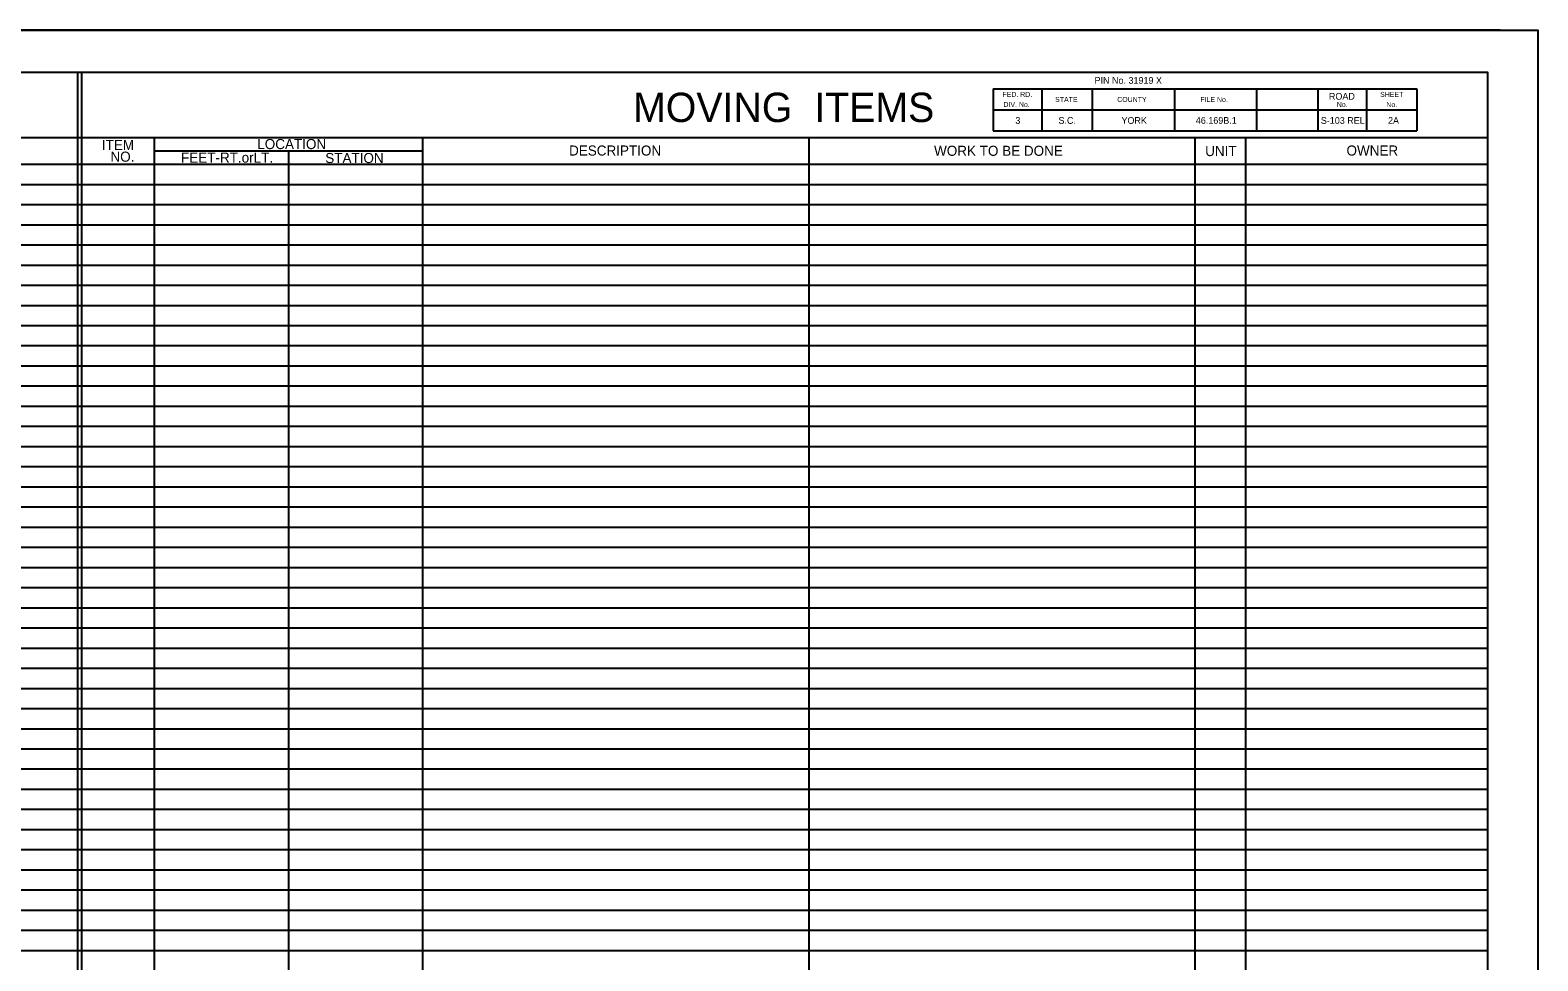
# Model space of a CAD drawing. Extents: x -796 to 2793, y -4650 to 4425.
# Drawn here: x 1884 to 2782, y -1829 to -1275 of the extents above; entities that cross this region are included whole.
import ezdxf

# ---------------------------------------------------------------- set-up
doc = ezdxf.new("R2010")
doc.units = 0
for name, color, linetype in [('RD_HC_CL', 7, 'Continuous'), ('RD_HC_Data', 7, 'Continuous'), ('RD_HC_Data_Tic', 7, 'Continuous')]:
    doc.layers.add(name, color=color, linetype=linetype)

msp = doc.modelspace()

# ---------------------------------------------------------------- linework, layer by layer
at = {"layer": 'RD_HC_CL'}
msp.add_lwpolyline([(986.5, -1275), (2782.45, -1275), (2782.45, -2375), (986.5, -2375)], close=True, dxfattribs=at)
at = {"layer": 'RD_HC_Data'}
for p, q in [((2760, -1275), (1000, -1275)), ((1000, -1275), (2760, -1275)), ((1912.65, -1300), (1912.65, -2350)), ((1915.15, -1300), (1915.15, -2350)), ((2457.95, -1310), (2457.95, -1335)), ((2457.95, -1310), (2710.45, -1310)), ((2486.95, -1310), (2486.95, -1322.5)), ((2516.95, -1310), (2516.95, -1322.5)), ((2565.95, -1310), (2565.95, -1322.5)), ((2614.95, -1310), (2614.95, -1322.5)), ((2651.45, -1310), (2651.45, -1322.5)), ((2680.45, -1310), (2680.45, -1322.5)), ((2710.45, -1310), (2710.45, -1335)), ((2457.95, -1322.5), (2710.45, -1322.5)), ((2486.95, -1322.5), (2486.95, -1335)), ((2516.95, -1322.5), (2516.95, -1335)), ((2565.95, -1322.5), (2565.95, -1335)), ((2614.95, -1322.5), (2614.95, -1335)), ((2651.45, -1322.5), (2651.45, -1335)), ((2680.45, -1322.5), (2680.45, -1335)), ((2457.95, -1335), (2710.45, -1335)), ((2752.45, -1339), (1077.45, -1339)), ((1958.45, -2350), (1958.45, -1339)), ((2118.45, -2350), (2118.45, -1339)), ((2348.45, -2350), (2348.45, -1339)), ((2578.45, -2350), (2578.45, -1339)), ((2608.45, -2350), (2608.45, -1339)), ((2752.45, -1355), (1077.45, -1355)), ((2118.45, -1347), (1958.45, -1347)), ((2038.45, -2350), (2038.45, -1347)), ((2752.45, -1367), (1077.45, -1367)), ((2752.45, -1379), (1077.45, -1379)), ((2752.45, -1391), (1077.45, -1391)), ((2752.45, -1403), (1077.45, -1403)), ((2752.45, -1415), (1077.45, -1415)), ((2752.45, -1427), (1077.45, -1427)), ((2752.45, -1439), (1077.45, -1439)), ((2752.45, -1451), (1077.45, -1451)), ((2752.45, -1463), (1077.45, -1463)), ((2752.45, -1475), (1077.45, -1475)), ((2752.45, -1487), (1077.45, -1487)), ((2752.45, -1499), (1077.45, -1499)), ((2752.45, -1511), (1077.45, -1511)), ((2752.45, -1523), (1077.45, -1523)), ((2752.45, -1535), (1077.45, -1535)), ((2752.45, -1547), (1077.45, -1547)), ((2752.45, -1559), (1077.45, -1559)), ((2752.45, -1571), (1077.45, -1571)), ((2752.45, -1583), (1077.45, -1583)), ((2752.45, -1595), (1077.45, -1595)), ((2752.45, -1607), (1077.45, -1607)), ((2752.45, -1619), (1077.45, -1619)), ((2752.45, -1631), (1077.45, -1631)), ((2752.45, -1643), (1077.45, -1643)), ((2752.45, -1655), (1077.45, -1655)), ((2752.45, -1667), (1077.45, -1667)), ((2752.45, -1679), (1077.45, -1679)), ((2752.45, -1691), (1077.45, -1691)), ((2752.45, -1703), (1077.45, -1703)), ((2752.45, -1715), (1077.45, -1715)), ((2752.45, -1727), (1077.45, -1727)), ((2752.45, -1739), (1077.45, -1739)), ((2752.45, -1751), (1077.45, -1751)), ((2752.45, -1763), (1077.45, -1763)), ((2752.45, -1775), (1077.45, -1775)), ((2752.45, -1787), (1077.45, -1787)), ((2752.45, -1799), (1077.45, -1799)), ((2752.45, -1811), (1077.45, -1811)), ((2752.45, -1823), (1077.45, -1823))]:
    msp.add_line(p, q, dxfattribs=at)
msp.add_lwpolyline([(1077.45, -1300), (2752.45, -1300), (2752.45, -2350), (1077.45, -2350)], close=True, dxfattribs=at)

# ---------------------------------------------------------------- texts
at = {"layer": 'RD_HC_Data_Tic'}
for s, height, p in [('PIN No. 31919 X   ', 4, (2518.42, -1306.91)), ('MOVING  ITEMS', 17.4999, (2243.55, -1329.7)), ('FED. RD.', 3, (2463.57, -1314.75)), ('DIV. No.', 3, (2464.19, -1320.75)), ('STATE', 3, (2494.97, -1317.75)), ('COUNTY', 3, (2531.94, -1317.75)), ('FILE No.', 3, (2581.45, -1317.75)), ('      ROAD      ', 4, (2649.09, -1316.4)), ('No.', 3, (2662.71, -1320.75)), ('SHEET', 3, (2688.53, -1314.75)), ('No.', 3, (2692.21, -1320.75)), ('3', 4, (2471.25, -1330.75)), ('S.C.', 4, (2496.93, -1330.75)), ('      YORK      ', 4, (2525.53, -1330.75)), ('   46.169B.1    ', 4, (2574.29, -1330.75)), ('   S-103 REL.   ', 4, (2648.73, -1330.75)), ('       2A       ', 4, (2682.8, -1330.75)), ('ITEM', 6, (1927.2, -1346.35)), ('LOCATION', 6, (2019.75, -1345.8)), ('DESCRIPTION', 6, (2205.45, -1349.65)), ('WORK TO BE DONE', 6, (2422.85, -1349.8)), ('UNIT', 6, (2584.3, -1349.95)), ('OWNER', 6, (2668.5, -1349.65)), ('NO.', 6, (1932.3, -1353.3)), ('FEET-RT.orLT.', 6, (1974.35, -1353.85)), ('STATION', 6, (2060.25, -1354.1))]:
    msp.add_text(s, height=height, dxfattribs=at).set_placement(p)

doc.saveas('drawing.dxf')
